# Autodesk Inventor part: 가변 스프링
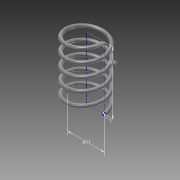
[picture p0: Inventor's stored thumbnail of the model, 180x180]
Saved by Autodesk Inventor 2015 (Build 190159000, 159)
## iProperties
Created: 2015-10
Part Number: 가변 스프링
Material: 강철, 연강
Document SubType Name: Modeling
Designer: PHO-02
Density: 7.85 g/cm^3
Appearance: 반연마
Mass: 1.05399 g
Surface Area: 5.43049 cm^2
Volume: 0.134266 cm^3
Author: PHO-02
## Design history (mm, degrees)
sketch "스케치2"
  geometry: L1 (0, 0)-(-5.5, 0); L2 (-5.5, 0)-(-5.5, 18.948); L3 (-5.5, 18.948)-(0, 18.948); L4 (0, 18.948)-(0, 0); C1 r 0.5 at (-5.5, 0)
  constraints: 8 end point, 2 parallel, 1 centre point, 1 coincident, 1 horizontal, 1 perpendicular
  dimensions: "d0" = 18.94782 distance between parallel lines of L3 L1 (derived); "d1" = 11 diameter of L2 L4; "d2" = 1 diameter of C1
feature "코일1" sketch "스케치2" pitch "d3" = 10; turns "d5" = 5; dims "d4" = 18.94782 (= d0), "d6" = 0, angle "d7" = 90 deg, angle "d8" = 90 deg, "d9" = 0, "d10" = 0
sketch "스케치3"
  geometry: L1 (6, 0)-(5, 0) reference; 1 further point
  constraints: 1 horizontal alignment
extrude "돌출1" cut sketch "스케치3" stored distance "d11" = 10; taper "d12" = 0 deg
node "작업 평면1"
sketch "스케치4"
  geometry: L1 (-0.5, 0)-(0.5, 0) reference; 1 further point
  constraints: 1 horizontal alignment
extrude "돌출2" cut sketch "스케치4" stored distance "d14" = 10; taper "d15" = 0 deg
node "솔리드1"
node "절단 모서리 투영1"
node "절단 모서리 투영2"
other parameters: "d13" = 90 deg
